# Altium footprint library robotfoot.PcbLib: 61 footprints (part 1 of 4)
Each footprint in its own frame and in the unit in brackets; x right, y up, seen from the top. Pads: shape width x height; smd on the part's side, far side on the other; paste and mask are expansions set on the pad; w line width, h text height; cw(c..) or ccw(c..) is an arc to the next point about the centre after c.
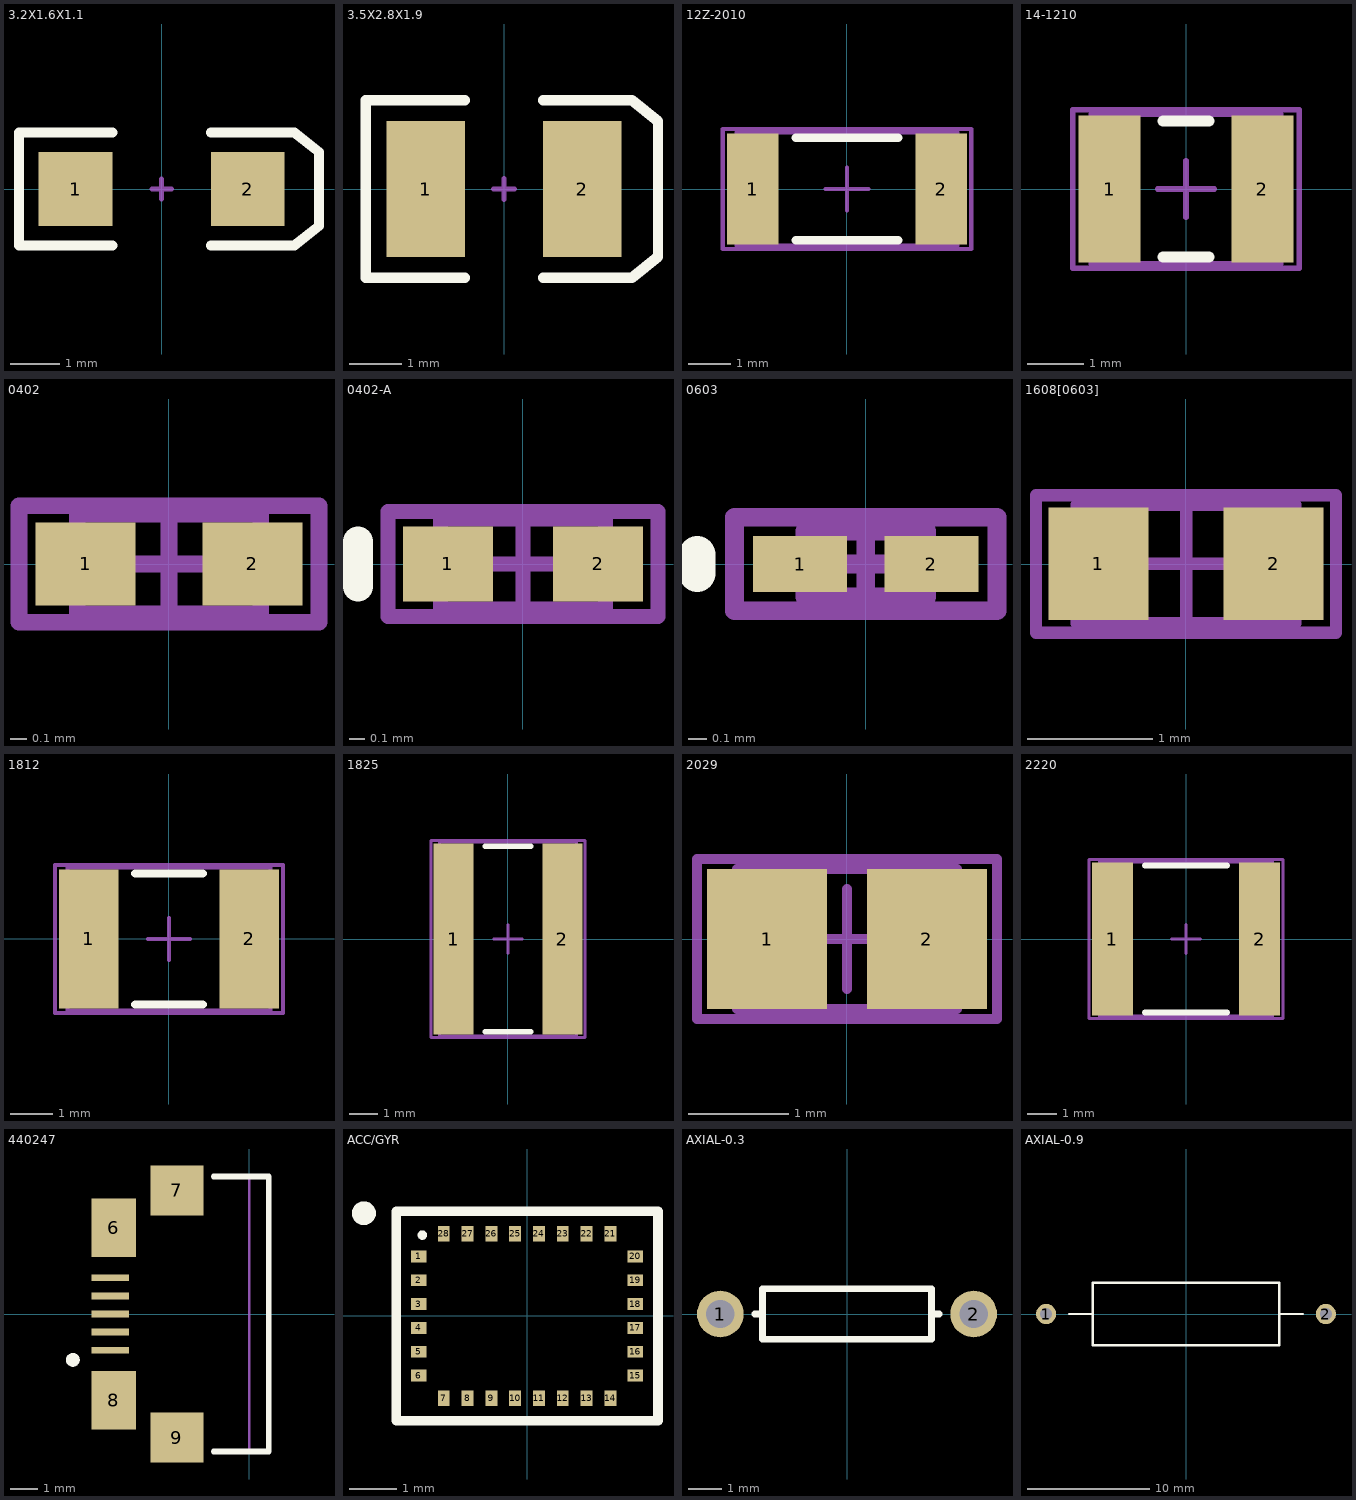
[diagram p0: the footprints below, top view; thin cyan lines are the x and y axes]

## 3.2X1.6X1.1 [mm] "SMT LED; 2 Flat Leads"
height 1.2
pads (2):
  rect 1.5x1.5 smd: 1(-1.75,0) 2(1.75,0)
Top Overlay:
  lines w0.2: -1,-1.15 -2.9,-1.15 -2.9,1.15 -1,1.15 ; 1,-1.15 2.7,-1.15 3.2,-0.75 3.2,0.75 2.7,1.15 1,1.15
Mechanical 1:
  lines w0.1: -0.2,0 0.2,0 ; 0,-0.2 0,0.2

## 3.5X2.8X1.9 [mm] "SM LED; 2 C-Bend Leads; Body 3.5 x 2.8 x 1.9 mm, inc leads (LxWxH typ)"
height 1.9
pads (2):
  rect 1.5x2.6 smd: 1(-1.5,0) 2(1.5,0)
Top Overlay:
  lines w0.2: -0.75,-1.7 -2.65,-1.7 -2.65,1.7 -0.75,1.7 ; 0.75,-1.7 2.45,-1.7 2.95,-1.3 2.95,1.3 2.45,1.7 0.75,1.7
Mechanical 1:
  lines w0.1: -0.2,0 0.2,0 ; 0,-0.2 0,0.2

## 12Z-2010 [mm] "Chip Resistor, Body 5.0x2.5mm, IPC High Density"
height 0.9
pads (2):
  rect 1.2x2.6 smd: 1(-2.2,0) 2(2.2,0)
Top Overlay:
  lines w0.2: -1.2,-1.2 1.2,-1.2 ; -1.2,1.2 1.2,1.2
Mechanical 13:
  lines w0.1: -2.575,-1.325 -2.575,1.325 2.575,1.325 2.575,-1.325 -2.575,-1.325
Mechanical 15:
  lines w0.1: -0.5,0 0.5,0 ; 0,-0.5 0,0.5 ; -2.9,-1.4 -2.9,1.4 2.9,1.4 2.9,-1.4 -2.9,-1.4
3D body: height 0.9, standoff 0, extent -2.575,-1.325 2.575,1.325

## 14-1210 [mm] "Chip Resistor, Body 3.2x2.5mm, IPC High Density"
height 0.9
pads (2):
  rect 1.1x2.6 smd: 1(-1.35,0) 2(1.35,0)
Top Overlay:
  lines w0.2: -0.4,-1.2 0.4,-1.2 ; -0.4,1.2 0.4,1.2
Mechanical 13:
  lines w0.1: -1.675,-1.32 1.675,-1.32 1.675,1.32 -1.675,1.32 -1.675,-1.32
Mechanical 15:
  lines w0.1: -0.5,0 0.5,0 ; 0,-0.5 0,0.5 ; -2,-1.4 2,-1.4 2,1.4 -2,1.4 -2,-1.4
3D body: height 0.9, standoff 0, extent -1.675,-1.32 1.675,1.32

## 0402 [mm] "Chip Capacitor, Body 1.0x0.5mm, IPC High Density"
height 1.3
pads (2):
  rect 0.6x0.5 smd: 1(-0.5,0) 2(0.5,0)
Mechanical 13:
  lines w0.1: -0.55,-0.3 -0.55,0.3 0.55,0.3 0.55,-0.3 -0.55,-0.3
Mechanical 15:
  lines w0.1: -0.3,0 0.3,0 ; 0,-0.3 0,0.3 ; -0.9,-0.35 -0.9,0.35 0.9,0.35 0.9,-0.35 -0.9,-0.35
3D body: height 1.3, standoff 0, extent -0.55,-0.3 0.55,0.3

## 0402-A [mm] "Chip Inductor, Body 1.0x0.5mm, IPC High Density"
height 0.55
pads (2):
  rect 0.6x0.5 smd: 1(-0.5,0) 2(0.5,0)
Top Overlay:
  lines w0.2: -1.1,-0.15 -1.1,0.15
Mechanical 13:
  lines w0.1: -0.55,-0.3 0.55,-0.3 0.55,0.3 -0.55,0.3 -0.55,-0.3
Mechanical 15:
  lines w0.1: -0.3,0 0.3,0 ; 0,-0.3 0,0.3 ; -0.9,-0.35 0.9,-0.35 0.9,0.35 -0.9,0.35 -0.9,-0.35
3D body: height 0.55, standoff 0, extent -0.55,-0.3 0.55,0.3

## 0603 [mm] "Chip Inductor, Body 0.6x0.3mm, IPC High Density"
height 0.55
pads (2):
  rect 0.5x0.3 smd: 1(-0.35,0) 2(0.35,0)
Top Overlay:
  lines w0.2: -0.9,-0.05 -0.9,0.05
Mechanical 13:
  lines w0.1: -0.325,-0.175 -0.325,0.175 0.325,0.175 0.325,-0.175 -0.325,-0.175
Mechanical 15:
  lines w0.1: -0.175,0 0.175,0 ; 0,-0.175 0,0.175 ; -0.7,-0.25 -0.7,0.25 0.7,0.25 0.7,-0.25 -0.7,-0.25
3D body: height 0.55, standoff 0, extent -0.325,-0.175 0.325,0.175

## 1608[0603] [mm] "Chip Capacitor, Body 1.6x0.8mm, IPC High Density"
height 1.3
pads (2):
  rect 0.8x0.9 smd: 1(-0.7,0) 2(0.7,0)
Mechanical 13:
  lines w0.1: -0.875,-0.475 0.875,-0.475 0.875,0.475 -0.875,0.475 -0.875,-0.475
Mechanical 15:
  lines w0.1: -0.475,0 0.475,0 ; 0,-0.475 0,0.475 ; -1.2,-0.55 1.2,-0.55 1.2,0.55 -1.2,0.55 -1.2,-0.55
3D body: height 1.3, standoff 0, extent -0.875,-0.475 0.875,0.475

## 1812 [mm] "Chip Capacitor, Body 4.5x3.2mm, IPC High Density"
height 1.4
pads (2):
  rect 1.4x3.3 smd: 1(-1.9,0) 2(1.9,0)
Top Overlay:
  lines w0.2: -0.8,-1.55 0.8,-1.55 ; -0.8,1.55 0.8,1.55
Mechanical 13:
  lines w0.1: -2.4,-1.7 2.4,-1.7 2.4,1.7 -2.4,1.7 -2.4,-1.7
Mechanical 15:
  lines w0.1: -0.5,0 0.5,0 ; 0,-0.5 0,0.5 ; -2.7,-1.75 2.7,-1.75 2.7,1.75 -2.7,1.75 -2.7,-1.75
3D body: height 1.4, standoff 0, extent -2.4,-1.7 2.4,1.7

## 1825 [mm] "Chip Capacitor, Body 4.5x6.4mm, IPC High Density"
height 1.4
pads (2):
  rect 1.4x6.7 smd: 1(-1.9,0) 2(1.9,0)
Top Overlay:
  lines w0.2: -0.8,-3.25 0.8,-3.25 ; -0.8,3.25 0.8,3.25
Mechanical 13:
  lines w0.1: -2.4,-3.4 2.4,-3.4 2.4,3.4 -2.4,3.4 -2.4,-3.4
Mechanical 15:
  lines w0.1: -0.5,0 0.5,0 ; 0,-0.5 0,0.5 ; -2.7,-3.45 2.7,-3.45 2.7,3.45 -2.7,3.45 -2.7,-3.45
3D body: height 1.4, standoff 0, extent -2.4,-3.4 2.4,3.4

## 2029 [mm] "Chip Inductor, Body 2.0x1.2mm, IPC High Density"
height 0.55
pads (2):
  rect 1.2x1.4 smd: 1(-0.8,0) 2(0.8,0)
Mechanical 13:
  lines w0.1: -1.1,-0.7 1.1,-0.7 1.1,0.7 -1.1,0.7 -1.1,-0.7
Mechanical 15:
  lines w0.1: -0.5,0 0.5,0 ; 0,-0.5 0,0.5 ; -1.5,-0.8 1.5,-0.8 1.5,0.8 -1.5,0.8 -1.5,-0.8
3D body: height 0.55, standoff 0, extent -1.1,-0.7 1.1,0.7

## 2220 [mm] "Chip Capacitor, Body 5.7x5.0mm, IPC High Density"
height 1.4
pads (2):
  rect 1.4x5.2 smd: 1(-2.5,0) 2(2.5,0)
Top Overlay:
  lines w0.2: -1.4,-2.5 1.4,-2.5 ; -1.4,2.5 1.4,2.5
Mechanical 13:
  lines w0.1: -2.95,-2.625 2.95,-2.625 2.95,2.625 -2.95,2.625 -2.95,-2.625
Mechanical 15:
  lines w0.1: -0.5,0 0.5,0 ; 0,-0.5 0,0.5 ; -3.3,-2.7 3.3,-2.7 3.3,2.7 -3.3,2.7 -3.3,-2.7
3D body: height 1.4, standoff 0, extent -2.95,-2.625 2.95,2.625

## 440247 [mm] "Connector; USB2.0, Type B, SM; 5 Position; Right Angle"
height 3.9
pads (9):
  rect 1.35x0.24 smd: 1(-5,-1.3) 2(-5,-0.65) 3(-5,0) 4(-5,0.65) 5(-5,1.3)
  rect 1.6x2.1 smd: 6(-4.875,3.1) 8(-4.875,-3.1)
  rect 1.9x1.8 smd: 7(-2.6,4.45) 9(-2.6,-4.45)
Top Overlay:
  circle w0.25: c-6.348,-1.651 r0.125
  lines w0.2: -1.27,-4.95 0.7,-4.95 0.7,4.95 -1.27,4.95
Mechanical 1:
  lines w0.1: 0,-4.95 0,4.95
  text "PCB Edge" at 0.432,-4.036 h0.25

## ACC/GYR [mm]
pads (28):
  rect 0.325x0.25 smd: 1(-2.275,1.25) 2(-2.275,0.75) 3(-2.275,0.25) 4(-2.275,-0.25) 5(-2.275,-0.75) 6(-2.275,-1.25) 15(2.275,-1.25) 16(2.275,-0.75) 17(2.275,-0.25) 18(2.275,0.25) 19(2.275,0.75) 20(2.275,1.25)
  rect 0.25x0.325 smd: 7(-1.75,-1.725) 8(-1.25,-1.725) 9(-0.75,-1.725) 10(-0.25,-1.725) 11(0.25,-1.725) 12(0.75,-1.725) 13(1.25,-1.725) 14(1.75,-1.725) 21(1.75,1.725) 22(1.25,1.725) 23(0.75,1.725) 24(0.25,1.725) 25(-0.25,1.725) 26(-0.75,1.725) 27(-1.25,1.725) 28(-1.75,1.725)
Top Overlay:
  circle w0.25: c-3.427,2.159 r0.125
  circle w0.1: c-2.2,1.7 r0.05
  lines w0.2: -2.75,-2.2 -2.75,2.2 2.75,2.2 2.75,-2.2 -2.75,-2.2

## AXIAL-0.3 [mm] "Axial Device, Thru-Hole; 2 Leads; 0.3 in Pin Spacing"
height 1.524
pads (2):
  round 1.4 hole 0.85: 1(-3.81,0) 2(3.81,0)
Top Overlay:
  lines w0.2: -2.769,0 -2.54,0 ; 2.769,0 2.54,0 ; 2.54,0 2.54,0.762 -2.54,0.762 -2.54,-0.762 2.54,-0.762 2.54,0

## AXIAL-0.9 [mm] "Axial Device, Thru-Hole; 2 Leads; 0.9 in Pin Spacing"
height 5.08
pads (2):
  round 1.65 hole 1: 1(-11.43,0) 2(11.43,0)
Top Overlay:
  lines w0.2: -9.525,0 -7.62,0 ; 7.62,0 9.525,0 ; -7.62,-2.54 7.62,-2.54 7.62,2.54 -7.62,2.54 -7.62,-2.54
